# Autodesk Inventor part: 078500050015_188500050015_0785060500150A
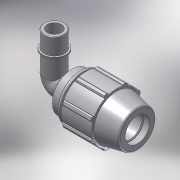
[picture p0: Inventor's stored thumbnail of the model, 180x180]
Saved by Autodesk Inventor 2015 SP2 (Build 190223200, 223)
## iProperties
Created: 2017-02
Part Number: 078500050015_188500050015_0785060500150A
Material: PVC-Piping
Description: PLASSON 90° ELBOW MALE ADAPTOR 50-1.1/2"
Document SubType Name: Modeling
Designer: KIM
Mass: 92.6774 g
Surface Area: 199.44 cm^2
Volume: 66.1981 cm^3
Density: 1.4 g/cm^3
Appearance: Smooth - White
Author: KIM
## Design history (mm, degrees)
derived "07850.ipt"
feature "Solid1::07850.ipt"
tag "TaggingFeature1"
body "Solid1"
other parameters: "d4" = 12, "d5" = 36, "d7" = 96, "d9" = 20.57143, "d11" = 4.8, "d13" = 120 deg, "d15" = 12 deg, "d16" = 83.52, "d18" = 2.5, "d19" = 35 deg, "d20" = 17.5 deg, "d21" = 89.28, "d23" = 0, "d25" = 360 deg, "d27" = 1.92, "d33" = 1, "d42" = 53.28, "d43" = 2.88, "d46" = 1.5, "d51" = 144, "d68" = 4.8, "d72" = 74, "d73" = 47.803, "d74" = 22, "d75" = 54.97345, "d76" = 33.4621, "d77" = 24.2, "d79" = 19.1212, "d80" = 1.43409, "d83" = 0, "d84" = 0, "d91" = 72, "d93" = 93, "d94" = 47.803, "d95" = 33.4621, "d96" = 14.4, "d97" = 50 deg, "E_" = 96, "A_" = 144, "l_" = 93, "l_2" = 22, "A_1" = 74, "R_" = 47.803
